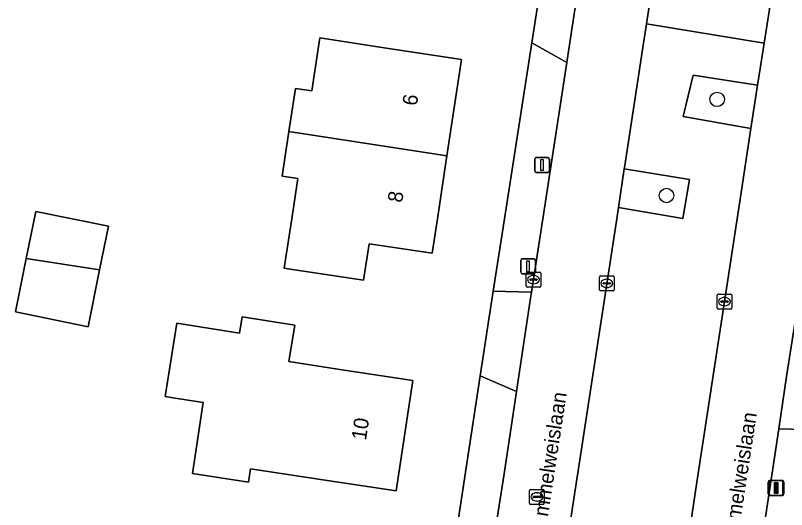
# Model space of a CAD drawing. Extents: x 161483 to 162250, y 379484 to 380833.
# Drawn here: x 161700.6 to 161752.7, y 380480.4 to 380513.7 of the extents above; entities that cross this region are included whole.
import ezdxf

# ---------------------------------------------------------------- set-up
doc = ezdxf.new("R2010")
doc.units = 0
for name, color, linetype in [('IMGEO_Boom', 7, 'Continuous'), ('IMGEO_Erf', 7, 'Continuous'), ('IMGEO_Groenvoorziening', 7, 'Continuous'), ('IMGEO_Kolk', 7, 'Continuous'), ('IMGEO_Lichtmast', 7, 'Continuous'), ('IMGEO_Openbare_ruimte_label', 7, 'Continuous'), ('IMGEO_Pand', 7, 'Continuous'), ('IMGEO_Pand_nummerreeks', 7, 'Continuous'), ('IMGEO_Rijbaan_lokaal_open', 7, 'Continuous'), ('IMGEO_Rioolput', 7, 'Continuous'), ('IMGEO_Voetpad_open', 7, 'Continuous')]:
    doc.layers.add(name, color=color, linetype=linetype)

msp = doc.modelspace()

# ---------------------------------------------------------------- linework, layer by layer
at = {"layer": 'IMGEO_Boom'}
for centre in [(161748.017, 380508.059), (161744.593, 380501.567)]:
    msp.add_circle(centre, 0.489, dxfattribs=at)
at = {"layer": 'IMGEO_Erf'}
for points in [[(161735.486, 380511.867), (161736.513, 380518.426), (161737.082, 380522.056)], [(161726.286, 380451.976), (161729.373, 380472.172), (161729.989, 380476.206), (161732.005, 380489.393), (161732.879, 380495.109), (161733.64, 380500), (161735.486, 380511.867)]]:
    msp.add_lwpolyline(points, dxfattribs=at)
for points in [[(161721.165, 380512.209), (161725.803, 380511.503), (161730.746, 380510.751), (161729.756, 380504.244), (161729.11, 380500), (161728.754, 380497.661), (161724.484, 380498.313), (161724.107, 380495.842), (161719.165, 380496.596), (161718.74, 380496.661), (161719.125, 380499.13), (161719.257, 380500), (161719.669, 380502.705), (161718.61, 380502.865), (161719.071, 380505.897), (161719.513, 380508.8), (161720.621, 380508.632)], [(161706.873, 380499.487), (161706.276, 380496.554), (161705.493, 380492.704), (161700.583, 380493.703), (161701.319, 380497.322), (161701.964, 380500.487)], [(161711.483, 380492.936), (161715.731, 380492.264), (161715.908, 380493.378), (161719.464, 380492.816), (161719.073, 380490.346), (161722.506, 380489.822), (161727.448, 380489.068), (161726.311, 380481.615), (161721.369, 380482.369), (161716.481, 380483.114), (161716.343, 380482.215), (161712.547, 380482.794), (161713.279, 380487.589), (161711.392, 380487.887), (161710.701, 380487.997)]]:
    msp.add_lwpolyline(points, close=True, dxfattribs=at)
at = {"layer": 'IMGEO_Groenvoorziening'}
for points in [[(161751.798, 380515.754), (161751.954, 380516.523), (161751.97, 380516.665), (161751.983, 380516.808), (161744.013, 380518.15), (161743.247, 380513.169), (161751.194, 380511.852)], [(161750.755, 380509.012), (161746.396, 380509.701), (161745.718, 380506.902), (161750.302, 380506.085)], [(161741.742, 380503.373), (161741.342, 380500.764), (161745.704, 380500.01), (161746.159, 380502.657)]]:
    msp.add_lwpolyline(points, close=True, dxfattribs=at)
msp.add_lwpolyline([(161745.711, 380476.014), (161746.655, 380482.196), (161749.364, 380500), (161749.564, 380501.311), (161750.302, 380506.085), (161745.718, 380506.902), (161746.396, 380509.701), (161750.755, 380509.012), (161750.95, 380510.274), (161751.194, 380511.852), (161743.247, 380513.169), (161743.044, 380511.848), (161741.775, 380503.591), (161741.742, 380503.373), (161746.159, 380502.657), (161745.704, 380500.01), (161741.342, 380500.764), (161741.225, 380500), (161737.808, 380477.707)], dxfattribs=at)
at = {"layer": 'IMGEO_Kolk'}
for p, q in [((161735.097, 380495.458), (161735.097, 380496.31)), ((161735.172, 380496.384), (161736.024, 380496.384)), ((161736.098, 380496.31), (161736.098, 380495.458)), ((161735.356, 380495.878), (161735.356, 380495.89)), ((161735.794, 380495.841), (161735.396, 380495.841)), ((161735.399, 380495.927), (161735.797, 380495.927)), ((161735.585, 380496.164), (161735.61, 380496.164)), ((161735.84, 380495.89), (161735.84, 380495.878)), ((161740.055, 380495.206), (161740.055, 380496.058)), ((161740.13, 380496.132), (161740.982, 380496.132)), ((161740.543, 380495.912), (161740.568, 380495.912)), ((161741.056, 380496.058), (161741.056, 380495.206)), ((161736.024, 380495.384), (161735.172, 380495.384)), ((161735.608, 380495.604), (161735.583, 380495.604)), ((161740.314, 380495.626), (161740.314, 380495.638)), ((161740.752, 380495.589), (161740.354, 380495.589)), ((161740.357, 380495.675), (161740.755, 380495.675)), ((161740.566, 380495.352), (161740.541, 380495.352)), ((161740.798, 380495.638), (161740.798, 380495.626)), ((161740.982, 380495.132), (161740.13, 380495.132)), ((161748.011, 380493.972), (161748.011, 380494.824)), ((161748.086, 380494.898), (161748.938, 380494.898)), ((161749.012, 380494.824), (161749.012, 380493.972)), ((161748.27, 380494.392), (161748.27, 380494.404)), ((161748.708, 380494.355), (161748.31, 380494.355)), ((161748.313, 380494.441), (161748.711, 380494.441)), ((161748.499, 380494.678), (161748.524, 380494.678)), ((161748.754, 380494.404), (161748.754, 380494.392)), ((161748.938, 380493.898), (161748.086, 380493.898)), ((161748.522, 380494.118), (161748.497, 380494.118))]:
    msp.add_line(p, q, dxfattribs=at)
for points in [[(161735.097, 380495.458), (161735.097, 380496.31)], [(161735.172, 380496.384), (161736.024, 380496.384)], [(161736.098, 380496.31), (161736.098, 380495.458)], [(161740.055, 380495.206), (161740.055, 380496.058)], [(161740.13, 380496.132), (161740.982, 380496.132)], [(161741.056, 380496.058), (161741.056, 380495.206)], [(161736.024, 380495.384), (161735.172, 380495.384)], [(161740.982, 380495.132), (161740.13, 380495.132)], [(161748.011, 380493.972), (161748.011, 380494.824)], [(161748.086, 380494.898), (161748.938, 380494.898)], [(161749.012, 380494.824), (161749.012, 380493.972)], [(161748.938, 380493.898), (161748.086, 380493.898)]]:
    msp.add_lwpolyline(points, dxfattribs=at)
for centre, radius, start, end in [((161735.174, 380496.308), 0.0765, 91.552, 178.448), ((161735.174, 380496.308), 0.0765, 91.552, 178.448), ((161736.022, 380496.308), 0.0765, 1.552, 88.448), ((161736.022, 380496.308), 0.0765, 1.552, 88.448), ((161735.396, 380495.887), 0.0403, 85.8775, 175.7526), ((161735.393, 380495.877), 0.0366, 178.938, 274.7102), ((161735.797, 380495.884), 0.043, 264.8664, 352.4533), ((161735.801, 380495.889), 0.0386, 1.7309, 96.639), ((161740.132, 380496.056), 0.0765, 91.552, 178.448), ((161740.132, 380496.056), 0.0765, 91.552, 178.448), ((161740.98, 380496.056), 0.0765, 1.552, 88.448), ((161740.98, 380496.056), 0.0765, 1.552, 88.448), ((161735.174, 380495.46), 0.0765, 181.552, 268.448), ((161735.174, 380495.46), 0.0765, 181.552, 268.448), ((161736.022, 380495.46), 0.0765, 271.552, 358.448), ((161736.022, 380495.46), 0.0765, 271.552, 358.448), ((161740.354, 380495.635), 0.0403, 85.8775, 175.7526), ((161740.351, 380495.625), 0.0366, 178.938, 274.7102), ((161740.755, 380495.632), 0.043, 264.8664, 352.4533), ((161740.759, 380495.637), 0.0386, 1.7309, 96.639), ((161740.132, 380495.208), 0.0765, 181.552, 268.448), ((161740.132, 380495.208), 0.0765, 181.552, 268.448), ((161740.98, 380495.208), 0.0765, 271.552, 358.448), ((161740.98, 380495.208), 0.0765, 271.552, 358.448), ((161748.088, 380494.822), 0.0765, 91.552, 178.448), ((161748.088, 380494.822), 0.0765, 91.552, 178.448), ((161748.936, 380494.822), 0.0765, 1.552, 88.448), ((161748.936, 380494.822), 0.0765, 1.552, 88.448), ((161748.31, 380494.401), 0.0403, 85.8775, 175.7526), ((161748.307, 380494.391), 0.0366, 178.938, 274.7102), ((161748.711, 380494.398), 0.043, 264.8664, 352.4533), ((161748.715, 380494.403), 0.0386, 1.7309, 96.639), ((161748.088, 380493.974), 0.0765, 181.552, 268.448), ((161748.088, 380493.974), 0.0765, 181.552, 268.448), ((161748.936, 380493.974), 0.0765, 271.552, 358.448), ((161748.936, 380493.974), 0.0765, 271.552, 358.448)]:
    msp.add_arc(centre, radius, start, end, dxfattribs=at)
for centre, major_axis, ratio, start_param, end_param in [((161735.584, 380495.884), (-0.387, 0.002), 0.722429, 4.712389, 7.853982), ((161735.609, 380495.884), (-0.39, 0.002), 0.717154, 1.570796, 4.712389), ((161740.542, 380495.632), (-0.387, 0.002), 0.722429, 4.712389, 7.853982), ((161740.567, 380495.632), (-0.39, 0.002), 0.717154, 1.570796, 4.712389), ((161748.498, 380494.398), (-0.387, 0.002), 0.722429, 4.712389, 7.853982), ((161748.523, 380494.398), (-0.39, 0.002), 0.717154, 1.570796, 4.712389)]:
    msp.add_ellipse(centre, major_axis=major_axis, ratio=ratio, start_param=start_param, end_param=end_param, dxfattribs=at)
at = {"layer": 'IMGEO_Lichtmast'}
for p, q in [((161735.788, 380504.126), (161736.578, 380504.126)), ((161736.578, 380504.126), (161735.788, 380504.126)), ((161735.688, 380503.226), (161735.688, 380504.026)), ((161735.688, 380504.026), (161735.688, 380503.226)), ((161736.678, 380504.026), (161736.678, 380503.226)), ((161736.678, 380503.226), (161736.678, 380504.026)), ((161736.578, 380503.126), (161735.788, 380503.126)), ((161735.788, 380503.126), (161736.578, 380503.126)), ((161734.739, 380496.38), (161734.739, 380497.18)), ((161734.739, 380497.18), (161734.739, 380496.38)), ((161734.839, 380497.28), (161735.629, 380497.28)), ((161735.629, 380497.28), (161734.839, 380497.28)), ((161735.729, 380497.18), (161735.729, 380496.38)), ((161735.729, 380496.38), (161735.729, 380497.18)), ((161735.629, 380496.28), (161734.839, 380496.28)), ((161734.839, 380496.28), (161735.629, 380496.28)), ((161751.463, 380481.415), (161751.463, 380482.215)), ((161751.463, 380482.215), (161751.463, 380481.415)), ((161751.563, 380482.315), (161752.353, 380482.315)), ((161752.353, 380482.315), (161751.563, 380482.315)), ((161751.641, 380482.308), (161752.431, 380482.308)), ((161752.431, 380482.308), (161751.641, 380482.308)), ((161752.453, 380482.215), (161752.453, 380481.415)), ((161752.453, 380481.415), (161752.453, 380482.215)), ((161751.541, 380481.408), (161751.541, 380482.208)), ((161751.541, 380482.208), (161751.541, 380481.408)), ((161752.531, 380482.208), (161752.531, 380481.408)), ((161752.531, 380481.408), (161752.531, 380482.208)), ((161752.353, 380481.315), (161751.563, 380481.315)), ((161751.563, 380481.315), (161752.353, 380481.315)), ((161752.431, 380481.308), (161751.641, 380481.308)), ((161751.641, 380481.308), (161752.431, 380481.308))]:
    msp.add_line(p, q, dxfattribs=at)
for points in [[(161736.108, 380504.001), (161736.258, 380504.001), (161736.258, 380503.251), (161736.108, 380503.251), (161736.108, 380504.001)], [(161735.159, 380497.155), (161735.309, 380497.155), (161735.309, 380496.405), (161735.159, 380496.405), (161735.159, 380497.155)], [(161751.883, 380482.19), (161752.033, 380482.19), (161752.033, 380481.44), (161751.883, 380481.44), (161751.883, 380482.19)], [(161751.961, 380482.183), (161752.111, 380482.183), (161752.111, 380481.433), (161751.961, 380481.433), (161751.961, 380482.183)]]:
    msp.add_lwpolyline(points, dxfattribs=at)
for centre, start, end in [((161735.788, 380504.026), 90, 180), ((161735.788, 380504.026), 90, 180), ((161736.578, 380504.026), 0, 90), ((161736.578, 380504.026), 360, 90), ((161735.788, 380503.226), 180, 270), ((161735.788, 380503.226), 180, 270), ((161736.578, 380503.226), 270, 0), ((161736.578, 380503.226), 270, 0), ((161734.839, 380497.18), 90, 180), ((161734.839, 380497.18), 90, 180), ((161735.629, 380497.18), 0, 90), ((161735.629, 380497.18), 360, 90), ((161734.839, 380496.38), 180, 270), ((161734.839, 380496.38), 180, 270), ((161735.629, 380496.38), 270, 0), ((161735.629, 380496.38), 270, 0), ((161751.563, 380482.215), 90, 180), ((161751.563, 380482.215), 90, 180), ((161751.641, 380482.208), 90, 180), ((161751.641, 380482.208), 90, 180), ((161752.353, 380482.215), 0, 90), ((161752.353, 380482.215), 360, 90), ((161752.431, 380482.208), 0, 90), ((161752.431, 380482.208), 360, 90), ((161751.563, 380481.415), 180, 270), ((161751.563, 380481.415), 180, 270), ((161751.641, 380481.408), 180, 270), ((161751.641, 380481.408), 180, 270), ((161752.353, 380481.415), 270, 0), ((161752.353, 380481.415), 270, 0), ((161752.431, 380481.408), 270, 0), ((161752.431, 380481.408), 270, 0)]:
    msp.add_arc(centre, 0.1, start, end, dxfattribs=at)
at = {"layer": 'IMGEO_Pand'}
for points in [[(161729.756, 380504.244), (161730.746, 380510.751), (161725.803, 380511.503), (161721.165, 380512.209), (161720.621, 380508.632), (161719.513, 380508.8), (161719.071, 380505.897)], [(161729.756, 380504.244), (161719.071, 380505.897), (161718.61, 380502.865), (161719.669, 380502.705), (161719.257, 380500), (161719.125, 380499.13), (161718.74, 380496.661), (161719.165, 380496.596), (161724.107, 380495.842), (161724.484, 380498.313), (161728.754, 380497.661), (161729.11, 380500)], [(161706.276, 380496.554), (161706.873, 380499.487), (161701.964, 380500.487), (161701.319, 380497.322)], [(161706.276, 380496.554), (161701.319, 380497.322), (161700.583, 380493.703), (161705.493, 380492.704)], [(161712.547, 380482.794), (161716.343, 380482.215), (161716.481, 380483.114), (161721.369, 380482.369), (161726.311, 380481.615), (161727.448, 380489.068), (161722.506, 380489.822), (161719.073, 380490.346), (161719.464, 380492.816), (161715.908, 380493.378), (161715.731, 380492.264), (161711.483, 380492.936), (161710.701, 380487.997), (161711.392, 380487.887), (161713.279, 380487.589)]]:
    msp.add_lwpolyline(points, close=True, dxfattribs=at)
at = {"layer": 'IMGEO_Rijbaan_lokaal_open'}
for points in [[(161739.434, 380521.028), (161739.045, 380518.432), (161737.956, 380511.156), (161737.863, 380510.556), (161736.234, 380500), (161735.469, 380495.044), (161735.406, 380494.637), (161734.457, 380488.318), (161733.623, 380482.759), (161732.522, 380475.779), (161731.907, 380471.88), (161731.699, 380470.562), (161729.579, 380456.467), (161728.874, 380451.915)], [(161733.427, 380448.661), (161733.536, 380449.72), (161734.23, 380454.128), (161734.359, 380454.949), (161734.535, 380456.068), (161735.018, 380459.271), (161735.441, 380462.069), (161736.99, 380472.333), (161737.2, 380473.726), (161737.36, 380474.784), (161737.621, 380476.484), (161737.808, 380477.707), (161741.225, 380500), (161741.342, 380500.764), (161741.742, 380503.373), (161741.775, 380503.591), (161743.044, 380511.848), (161743.247, 380513.169), (161744.013, 380518.15), (161744.054, 380518.542)], [(161746.487, 380448.105), (161746.564, 380448.816), (161747.536, 380455.574), (161748.798, 380463.6), (161749.749, 380469.769), (161750.339, 380473.597), (161750.589, 380475.219), (161752.178, 380485.804), (161752.708, 380489.333), (161753.226, 380492.628), (161754.384, 380500), (161755.056, 380504.275), (161755.602, 380507.939), (161756.631, 380514.835), (161757.103, 380518.001)], [(161751.983, 380516.808), (161751.97, 380516.665), (161751.954, 380516.523), (161751.798, 380515.754), (161751.194, 380511.852), (161750.95, 380510.274), (161750.755, 380509.012), (161750.302, 380506.085), (161749.564, 380501.311), (161749.364, 380500), (161746.655, 380482.196), (161745.711, 380476.014), (161744.957, 380471.08), (161744.753, 380469.744), (161744.338, 380467.025), (161744.263, 380466.534), (161742.327, 380453.656), (161742.204, 380452.837), (161741.522, 380448.297)]]:
    msp.add_lwpolyline(points, dxfattribs=at)
at = {"layer": 'IMGEO_Rioolput'}
for p, q in [((161735.405, 380481.706), (161736.257, 380481.706)), ((161735.33, 380480.78), (161735.33, 380481.632)), ((161735.589, 380481.2), (161735.589, 380481.212)), ((161735.632, 380481.249), (161736.03, 380481.249)), ((161735.818, 380481.486), (161735.843, 380481.486)), ((161736.073, 380481.212), (161736.073, 380481.2)), ((161736.331, 380481.632), (161736.331, 380480.78)), ((161736.257, 380480.706), (161735.405, 380480.706)), ((161736.027, 380481.163), (161735.629, 380481.163)), ((161735.841, 380480.926), (161735.816, 380480.926))]:
    msp.add_line(p, q, dxfattribs=at)
for points in [[(161735.405, 380481.706), (161736.257, 380481.706)], [(161735.33, 380480.78), (161735.33, 380481.632)], [(161736.331, 380481.632), (161736.331, 380480.78)], [(161736.257, 380480.706), (161735.405, 380480.706)]]:
    msp.add_lwpolyline(points, dxfattribs=at)
for centre, radius, start, end in [((161735.407, 380481.63), 0.0765, 91.552, 178.448), ((161735.407, 380481.63), 0.0765, 91.552, 178.448), ((161736.255, 380481.63), 0.0765, 1.552, 88.448), ((161736.255, 380481.63), 0.0765, 1.552, 88.448), ((161735.629, 380481.209), 0.0403, 85.8775, 175.7526), ((161735.626, 380481.199), 0.0366, 178.938, 274.7102), ((161736.03, 380481.206), 0.043, 264.8664, 352.4533), ((161736.034, 380481.211), 0.0386, 1.7309, 96.639), ((161735.407, 380480.782), 0.0765, 181.552, 268.448), ((161735.407, 380480.782), 0.0765, 181.552, 268.448), ((161736.255, 380480.782), 0.0765, 271.552, 358.448), ((161736.255, 380480.782), 0.0765, 271.552, 358.448)]:
    msp.add_arc(centre, radius, start, end, dxfattribs=at)
for centre, major_axis, ratio, start_param, end_param in [((161735.817, 380481.206), (-0.387, 0.002), 0.722429, 4.712389, 7.853982), ((161735.842, 380481.206), (-0.39, 0.002), 0.717154, 1.570796, 4.712389)]:
    msp.add_ellipse(centre, major_axis=major_axis, ratio=ratio, start_param=start_param, end_param=end_param, dxfattribs=at)
at = {"layer": 'IMGEO_Voetpad_open'}
for points in [[(161737.863, 380510.556), (161737.956, 380511.156), (161739.045, 380518.432), (161736.513, 380518.426), (161735.486, 380511.867)], [(161737.863, 380510.556), (161735.486, 380511.867), (161733.64, 380500), (161732.879, 380495.109), (161735.469, 380495.044), (161736.234, 380500)], [(161732.005, 380489.393), (161734.457, 380488.318), (161735.406, 380494.637), (161735.469, 380495.044), (161732.879, 380495.109)], [(161755.69, 380491.68), (161753.226, 380492.628), (161752.708, 380489.333), (161752.178, 380485.804), (161754.766, 380485.737)], [(161732.005, 380489.393), (161729.989, 380476.206), (161732.522, 380475.779), (161733.623, 380482.759), (161734.457, 380488.318)], [(161750.339, 380473.597), (161752.696, 380472.423), (161754.766, 380485.737), (161752.178, 380485.804), (161750.589, 380475.219)]]:
    msp.add_lwpolyline(points, close=True, dxfattribs=at)

# ---------------------------------------------------------------- texts
at = {"layer": 'IMGEO_Openbare_ruimte_label'}
for p in [(161736.329, 380478.222), (161749.178, 380476.858)]:
    msp.add_text('Semmelweislaan', height=1, rotation=81.3105, dxfattribs=at).set_placement(p)
at = {"layer": 'IMGEO_Pand_nummerreeks'}
for s, rotation, p in [('6', 81.3473, (161727.715, 380507.586)), ('8', 81.3473, (161726.72, 380501.045)), ('10', 81.3261, (161724.278, 380484.997))]:
    msp.add_text(s, height=1, rotation=rotation, dxfattribs=at).set_placement(p)

doc.saveas('drawing.dxf')
